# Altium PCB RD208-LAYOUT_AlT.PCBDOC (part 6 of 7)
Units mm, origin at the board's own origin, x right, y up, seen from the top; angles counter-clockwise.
Board outline 240 x 150 mm, 6 copper layers (TOP, Mid-Layer 1, Mid-Layer 2, Mid-Layer 3, Mid-Layer 4, BOTTOM), stack 1.422 mm thick; 773 components, 409 nets, 3936 pads, 97 vias.
Unrouted connection lines stored in the file: 1.
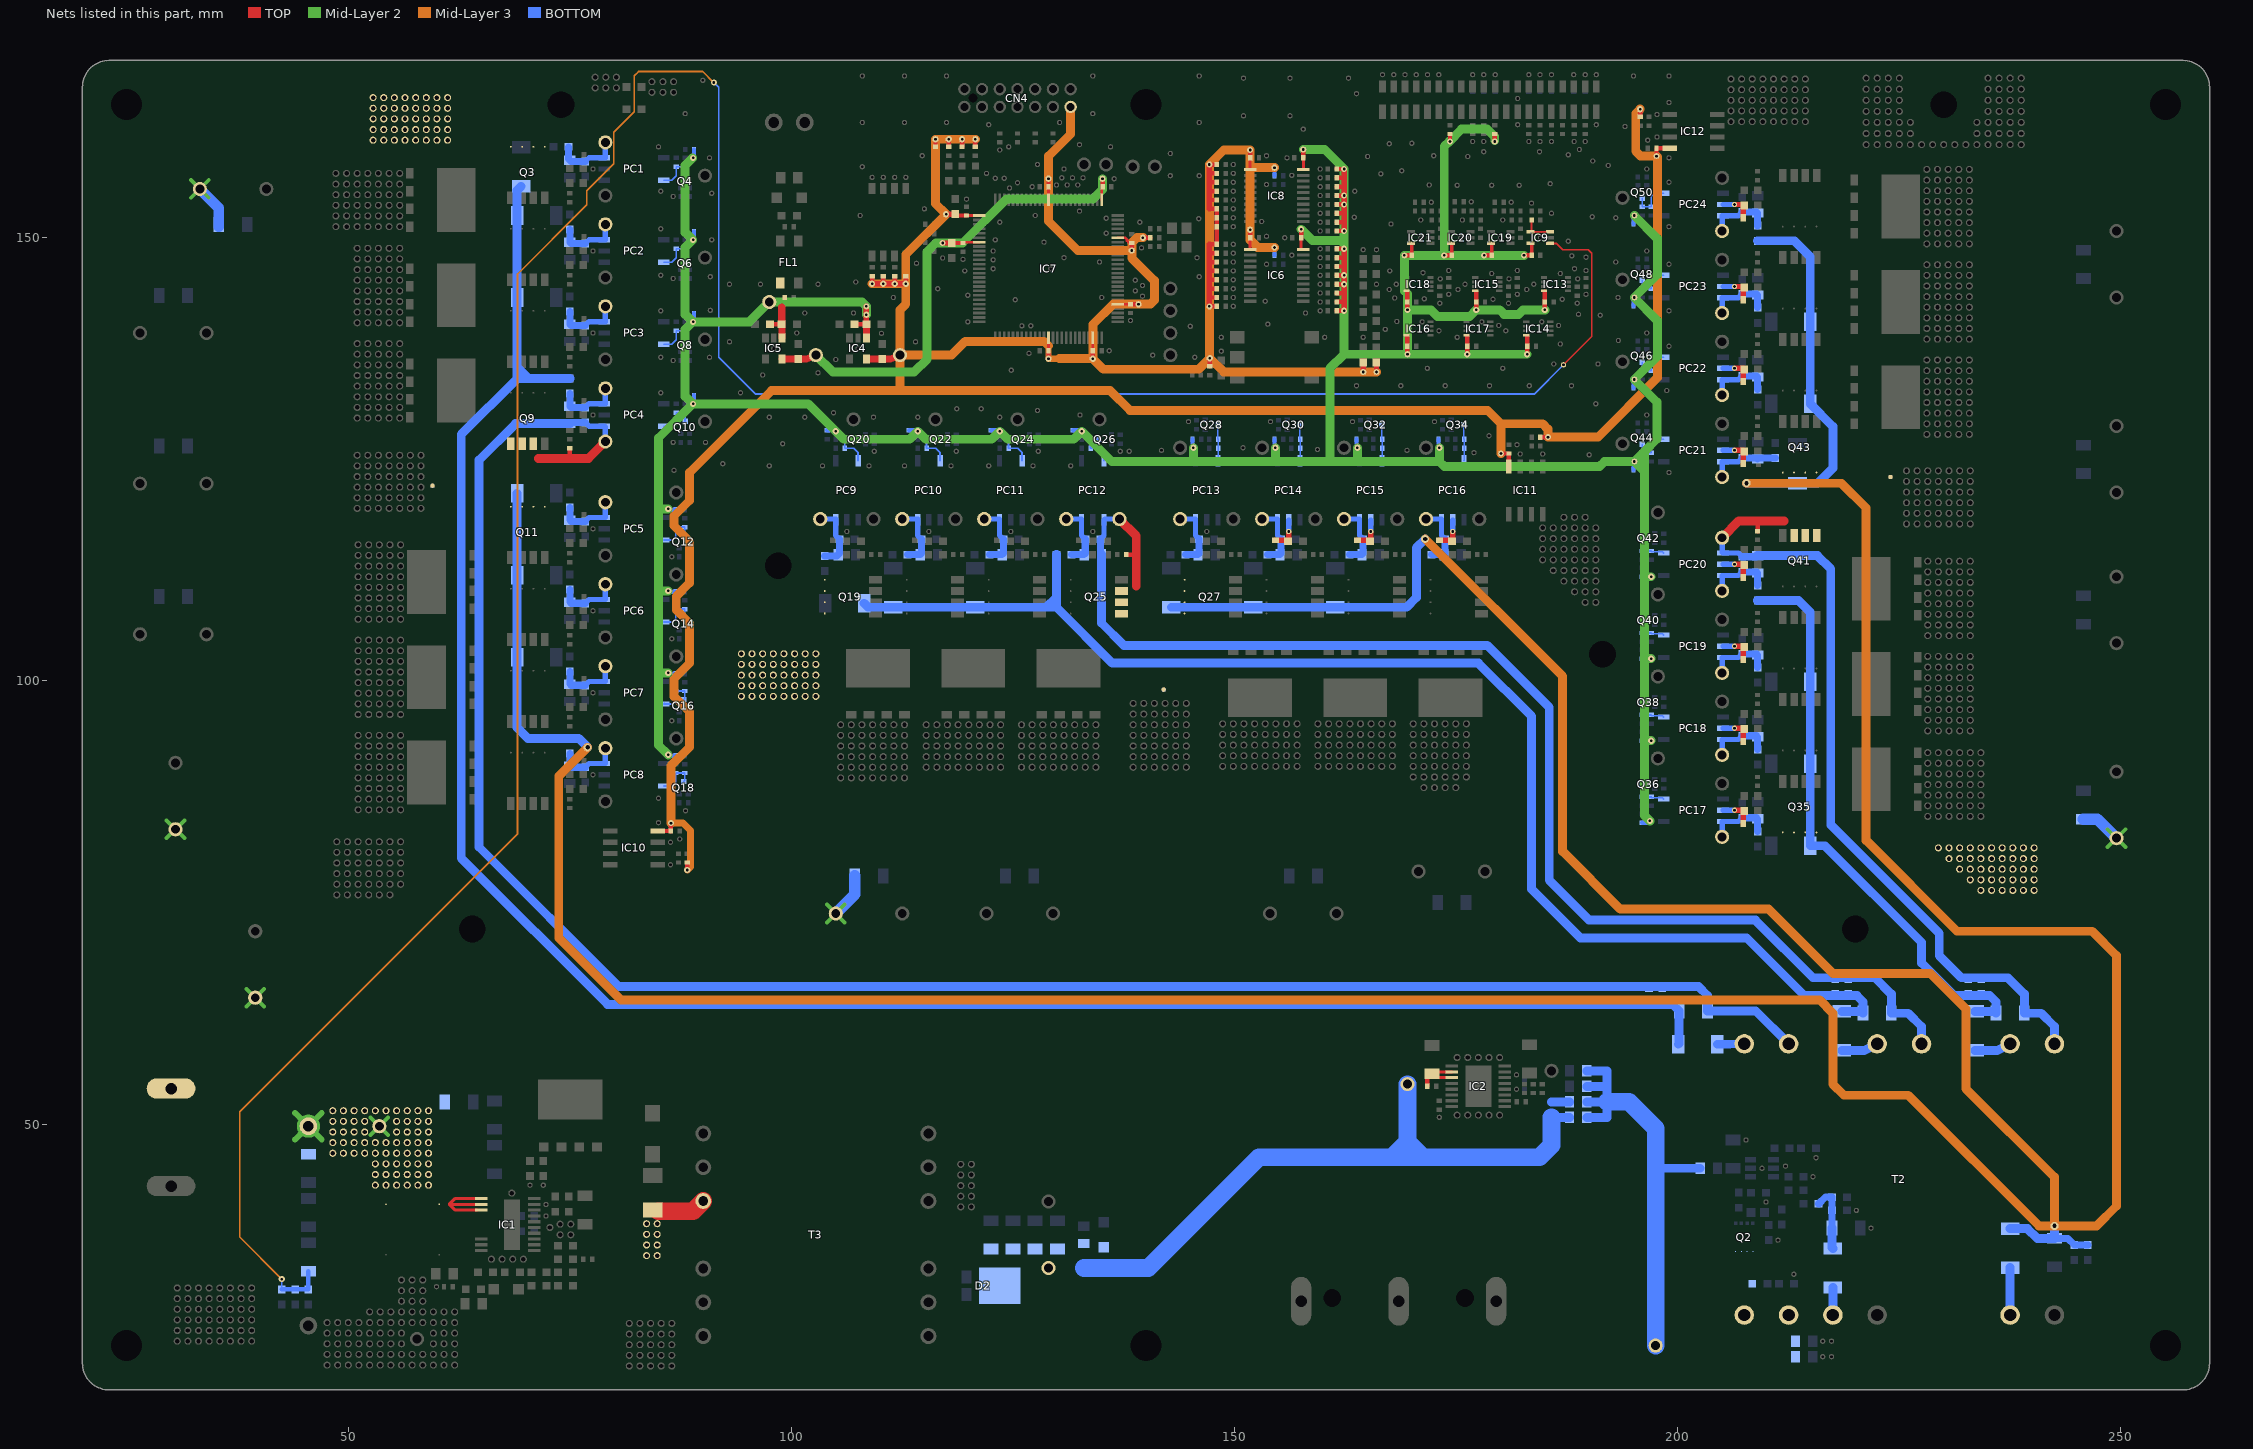
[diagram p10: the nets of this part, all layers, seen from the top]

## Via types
v1: diameter 0.7, hole 0.3, TOP to BOTTOM, 92 vias
v2: diameter 0.9, hole 0.5, TOP to BOTTOM, 4 vias
v3: diameter 1.6, hole 1, TOP to BOTTOM, 1 vias

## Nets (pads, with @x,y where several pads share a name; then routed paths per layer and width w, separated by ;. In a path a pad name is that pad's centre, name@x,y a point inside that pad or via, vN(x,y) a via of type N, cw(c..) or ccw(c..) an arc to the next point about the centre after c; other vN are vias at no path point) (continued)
PC_GD_V6: D63.K pad.@156.1,116.85 PC14.5 R173.1 | length 3.9
  TOP w0.6: D63.K@154.6,115.85 155.9,115.85 R173.1@156,115.75 156.1,115.85 pad.@156.1,116.85
  BOTTOM w0.6: pad.@156.1,116.85 PC14.5@156.1,118.15
PC_GD_V7: D64.K pad.@165.35,116.85 PC15.5 R174.1 | length 3.9
  TOP w0.6: D64.K@163.85,115.85 165.15,115.85 R174.1@165.25,115.75 165.35,115.85 pad.@165.35,116.85
  BOTTOM w0.6: pad.@165.35,116.85 PC15.5@165.35,118.15
PC_GD_V8: D65.K pad.@174.6,116.85 PC16.5 R175.1 | length 3.9
  TOP w0.6: D65.K@173.1,115.85 174.4,115.85 R175.1@174.5,115.75 174.6,115.85 pad.@174.6,116.85
  BOTTOM w0.6: pad.@174.6,116.85 PC16.5@174.6,118.15
PC_GD_W1: D66.K pad.@206.4,85.4 PC17.5 R184.1 | length 3.9
  TOP w0.6: pad.@206.4,85.4 207.4,85.4 R184.1@207.5,85.3 207.4,85.2 D66.K@207.4,83.9
  BOTTOM w0.6: PC17.5@205.1,85.4 pad.@206.4,85.4
PC_GD_W2: D67.K pad.@206.4,94.65 PC18.5 R185.1 | length 3.9
  TOP w0.6: pad.@206.4,94.65 207.4,94.65 R185.1@207.5,94.55 207.4,94.45 D67.K@207.4,93.15
  BOTTOM w0.6: PC18.5@205.1,94.65 pad.@206.4,94.65
PC_GD_W3: D68.K pad.@206.4,103.9 PC19.5 R186.1 | length 3.9
  TOP w0.6: pad.@206.4,103.9 207.4,103.9 R186.1@207.5,103.8 207.4,103.7 D68.K@207.4,102.4
  BOTTOM w0.6: PC19.5@205.1,103.9 pad.@206.4,103.9
PC_GD_W4: D69.K pad.@206.4,113.15 PC20.5 R187.1 | length 3.9
  TOP w0.6: pad.@206.4,113.15 207.4,113.15 R187.1@207.5,113.05 207.4,112.95 D69.K@207.4,111.65
  BOTTOM w0.6: PC20.5@205.1,113.15 pad.@206.4,113.15
PC_GD_W5: D70.K pad.@206.4,126 PC21.5 R188.1 | length 3.9
  TOP w0.6: pad.@206.4,126 207.4,126 R188.1@207.5,125.9 207.4,125.8 D70.K@207.4,124.5
  BOTTOM w0.6: PC21.5@205.1,126 pad.@206.4,126
PC_GD_W6: D71.K pad.@206.4,135.25 PC22.5 R189.1 | length 3.9
  TOP w0.6: pad.@206.4,135.25 207.4,135.25 R189.1@207.5,135.15 207.4,135.05 D71.K@207.4,133.75
  BOTTOM w0.6: PC22.5@205.1,135.25 pad.@206.4,135.25
PC_GD_W7: D72.K pad.@206.4,144.5 PC23.5 R190.1 | length 3.9
  TOP w0.6: pad.@206.4,144.5 207.4,144.5 R190.1@207.5,144.4 207.4,144.3 D72.K@207.4,143
  BOTTOM w0.6: PC23.5@205.1,144.5 pad.@206.4,144.5
PC_GD_W8: D73.K pad.@206.4,153.75 PC24.5 R191.1 | length 3.9
  TOP w0.6: pad.@206.4,153.75 207.4,153.75 R191.1@207.5,153.65 207.4,153.55 D73.K@207.4,152.25
  BOTTOM w0.6: PC24.5@205.1,153.75 pad.@206.4,153.75
PC_V_U1: C47.1 C112.1 PC1.6 R80.1 TP25.1 | length 7.5
  BOTTOM w0.6: C112.1@76.75,158.6 77.17,159.02 PC1.6@78.9,159.02 79,159.02 TP25.1@79,160.75
  BOTTOM w0.8: R80.1@74.85,160.25 74.85,158.875 C47.1@75,158.725 75.125,158.6 C112.1@76.75,158.6
PC_V_U2: C50.1 C113.1 PC2.6 R82.1 TP26.1 | length 7.4
  BOTTOM w0.6: C113.1@76.75,149.35 77.17,149.77 PC2.6@78.9,149.77 79,149.77 TP26.1@79,151.5
  BOTTOM w0.8: R82.1@75,150.9 C50.1@75,149.475 75.125,149.35 C113.1@76.75,149.35
PC_V_U3: C53.1 C114.1 PC3.6 R84.1 TP27.1 | length 7.4
  BOTTOM w0.6: C114.1@76.75,140.1 77.17,140.52 PC3.6@78.9,140.52 79,140.52 TP27.1@79,142.25
  BOTTOM w0.8: R84.1@75,141.65 C53.1@75,140.225 75.125,140.1 C114.1@76.75,140.1
PC_V_U4: C55.1 C115.1 PC4.6 R86.1 TP28.1 | length 7.4
  BOTTOM w0.6: C115.1@76.75,130.85 77.17,131.27 PC4.6@78.9,131.27 79,131.27 TP28.1@79,133
  BOTTOM w0.8: R86.1@75,132.4 C55.1@75,130.975 75.125,130.85 C115.1@76.75,130.85
PC_V_U5: C57.1 C116.1 PC5.6 R88.1 TP29.1 | length 7.4
  BOTTOM w0.6: C116.1@76.75,118 77.17,118.42 PC5.6@78.9,118.42 79,118.42 TP29.1@79,120.15
  BOTTOM w0.8: R88.1@75,119.55 C57.1@75,118.125 75.125,118 C116.1@76.75,118
PC_V_U6: C58.1 C117.1 PC6.6 R90.1 TP30.1 | length 7.4
  BOTTOM w0.6: C117.1@76.75,108.75 77.17,109.17 PC6.6@78.9,109.17 79,109.17 TP30.1@79,110.9
  BOTTOM w0.8: R90.1@75,110.3 C58.1@75,108.875 75.125,108.75 C117.1@76.75,108.75
PC_V_U7: C59.1 C118.1 PC7.6 R92.1 TP31.1 | length 7.4
  BOTTOM w0.6: C118.1@76.75,99.5 77.17,99.92 PC7.6@78.9,99.92 79,99.92 TP31.1@79,101.65
  BOTTOM w0.8: R92.1@75,101.05 C59.1@75,99.625 75.125,99.5 C118.1@76.75,99.5
PC_V_U8: C60.1 C119.1 PC8.6 R94.1 TP32.1 | length 7.4
  BOTTOM w0.6: C119.1@76.75,90.25 77.17,90.67 PC8.6@78.9,90.67 79,90.67 TP32.1@79,92.4
  BOTTOM w0.8: R94.1@75,91.8 C60.1@75,90.375 75.125,90.25 C119.1@76.75,90.25
PC_V_V1: C62.1 C104.1 PC9.6 R96.1 TP41.1 | length 7.5
  BOTTOM w0.6: TP41.1@103.25,118.25 104.98,118.25 PC9.6@104.98,118.15 104.98,116.42 C104.1@105.4,116
  BOTTOM w0.8: R96.1@103.75,114.1 105.125,114.1 C62.1@105.275,114.25 105.4,114.375 C104.1@105.4,116
PC_V_V2: C64.1 C105.1 PC10.6 R98.1 TP42.1 | length 7.4
  BOTTOM w0.6: TP42.1@112.5,118.25 114.23,118.25 PC10.6@114.23,118.15 114.23,116.42 C105.1@114.65,116
  BOTTOM w0.8: R98.1@113.1,114.25 C64.1@114.525,114.25 114.65,114.375 C105.1@114.65,116
PC_V_V3: C68.1 C106.1 PC11.6 R101.1 TP43.1 | length 7.4
  BOTTOM w0.6: TP43.1@121.75,118.25 123.48,118.25 PC11.6@123.48,118.15 123.48,116.42 C106.1@123.9,116
  BOTTOM w0.8: R101.1@122.35,114.25 C68.1@123.775,114.25 123.9,114.375 C106.1@123.9,116
PC_V_V4: C70.1 C107.1 PC12.6 R103.1 TP44.1 | length 7.4
  BOTTOM w0.6: TP44.1@131,118.25 132.73,118.25 PC12.6@132.73,118.15 132.73,116.42 C107.1@133.15,116
  BOTTOM w0.8: R103.1@131.6,114.25 C70.1@133.025,114.25 133.15,114.375 C107.1@133.15,116
PC_V_V5: C72.1 C108.1 PC13.6 R104.1 TP45.1 | length 7.4
  BOTTOM w0.6: TP45.1@143.85,118.25 145.58,118.25 PC13.6@145.58,118.15 145.58,116.42 C108.1@146,116
  BOTTOM w0.8: R104.1@144.45,114.25 C72.1@145.875,114.25 146,114.375 C108.1@146,116
PC_V_V6: C73.1 C109.1 PC14.6 R106.1 TP46.1 | length 7.4
  BOTTOM w0.6: TP46.1@153.1,118.25 154.83,118.25 PC14.6@154.83,118.15 154.83,116.42 C109.1@155.25,116
  BOTTOM w0.8: R106.1@153.7,114.25 C73.1@155.125,114.25 155.25,114.375 C109.1@155.25,116
PC_V_V7: C74.1 C110.1 PC15.6 R108.1 TP47.1 | length 7.4
  BOTTOM w0.6: TP47.1@162.35,118.25 164.08,118.25 PC15.6@164.08,118.15 164.08,116.42 C110.1@164.5,116
  BOTTOM w0.8: R108.1@162.95,114.25 C74.1@164.375,114.25 164.5,114.375 C110.1@164.5,116
PC_V_V8: C76.1 C111.1 PC16.6 R110.1 TP48.1 | length 7.4
  BOTTOM w0.6: TP48.1@171.6,118.25 173.33,118.25 PC16.6@173.33,118.15 173.33,116.42 C111.1@173.75,116
  BOTTOM w0.8: R110.1@172.2,114.25 C76.1@173.625,114.25 173.75,114.375 C111.1@173.75,116
PC_V_W1: C77.1 C120.1 PC17.6 R112.1 TP57.1 | length 7.4
  BOTTOM w0.6: TP57.1@205,82.4 205,84.13 PC17.6@205.1,84.13 206.83,84.13 C120.1@207.25,84.55
  BOTTOM w0.8: C120.1@207.25,84.55 208.875,84.55 C77.1@209,84.425 R112.1@209,83
PC_V_W2: C79.1 C121.1 PC18.6 R114.1 TP58.1 | length 7.4
  BOTTOM w0.6: TP58.1@205,91.65 205,93.38 PC18.6@205.1,93.38 206.83,93.38 C121.1@207.25,93.8
  BOTTOM w0.8: C121.1@207.25,93.8 208.875,93.8 C79.1@209,93.675 R114.1@209,92.25
PC_V_W3: C81.1 C122.1 PC19.6 R116.1 TP59.1 | length 7.4
  BOTTOM w0.6: TP59.1@205,100.9 205,102.63 PC19.6@205.1,102.63 206.83,102.63 C122.1@207.25,103.05
  BOTTOM w0.8: C122.1@207.25,103.05 208.875,103.05 C81.1@209,102.925 R116.1@209,101.5
PC_V_W4: C83.1 C123.1 PC20.6 R118.1 TP60.1 | length 7.4
  BOTTOM w0.6: TP60.1@205,110.15 205,111.88 PC20.6@205.1,111.88 206.83,111.88 C123.1@207.25,112.3
  BOTTOM w0.8: C123.1@207.25,112.3 208.875,112.3 C83.1@209,112.175 R118.1@209,110.75
PC_V_W5: C85.1 C124.1 PC21.6 R120.1 TP61.1 | length 8
  BOTTOM w0.6: TP61.1@205,123 205,124.73 PC21.6@205.1,124.73 206.83,124.73 C124.1@207.25,125.15
  BOTTOM w0.8: C124.1@207.25,125.15 208.875,125.15 C85.1@209,125.025 209.125,125.15 R120.1@211,125.15
PC_V_W6: C86.1 C125.1 PC22.6 R122.1 TP62.1 | length 7.4
  BOTTOM w0.6: TP62.1@205,132.25 205,133.98 PC22.6@205.1,133.98 206.83,133.98 C125.1@207.25,134.4
  BOTTOM w0.8: C125.1@207.25,134.4 208.875,134.4 C86.1@209,134.275 R122.1@209,132.85
PC_V_W7: C87.1 C126.1 PC23.6 R124.1 TP63.1 | length 7.4
  BOTTOM w0.6: TP63.1@205,141.5 205,143.23 PC23.6@205.1,143.23 206.83,143.23 C126.1@207.25,143.65
  BOTTOM w0.8: C126.1@207.25,143.65 208.875,143.65 C87.1@209,143.525 R124.1@209,142.1
PC_V_W8: C88.1 C127.1 PC24.6 R126.1 TP64.1 | length 7.4
  BOTTOM w0.6: TP64.1@205,150.75 205,152.48 PC24.6@205.1,152.48 206.83,152.48 C127.1@207.25,152.9
  BOTTOM w0.8: C127.1@207.25,152.9 208.875,152.9 C88.1@209,152.775 R126.1@209,151.35
PC_VGS_U1: C142.2 PC1.3 Q4.3 R337.2 | length 4.6
  BOTTOM w0.2: PC1.3@85.6,156.48 86.5,156.48 87,156.98 R337.2@87,158 C142.2@88,158 Q4.3@88,157.05
PC_VGS_U2: C143.2 PC2.3 Q6.3 R338.2 | length 4.6
  BOTTOM w0.2: PC2.3@85.6,147.23 86.5,147.23 87,147.73 R338.2@87,148.75 C143.2@88,148.75 Q6.3@88,147.8
PC_VGS_U3: C144.2 PC3.3 Q8.3 R339.2 | length 4.6
  BOTTOM w0.2: PC3.3@85.6,137.98 86.5,137.98 87,138.48 R339.2@87,139.5 C144.2@88,139.5 Q8.3@88,138.55
PC_VGS_U4: C145.2 PC4.3 Q10.3 R340.2 | length 4.6
  BOTTOM w0.2: PC4.3@85.6,128.73 86.5,128.73 87,129.23 R340.2@87,130.25 C145.2@88,130.25 Q10.3@88,129.3
PC_VGS_U5: C146.2 PC5.3 Q12.3 R341.2 | length 4.6
  BOTTOM w0.2: PC5.3@85.6,115.88 86.55,115.88 86.95,116.28 R341.2@86.95,117.35 C146.2@87.95,117.35 87.95,116.5 Q12.3@87.85,116.4
PC_VGS_U6: C147.2 PC6.3 Q14.3 R342.2 | length 4.6
  BOTTOM w0.2: PC6.3@85.6,106.63 86.55,106.63 86.95,107.03 R342.2@86.95,108.1 C147.2@87.95,108.1 87.95,107.25 Q14.3@87.85,107.15
PC_VGS_U7: C148.2 PC7.3 Q16.3 R343.2 | length 4.7
  BOTTOM w0.2: PC7.3@85.67,97.45 PC7.3@85.6,97.38 86.55,97.38 86.95,97.78 R343.2@86.95,98.85 C148.2@87.95,98.85 87.95,98 Q16.3@87.85,97.9
PC_VGS_U8: C149.2 PC8.3 Q18.3 R344.2 | length 4.6
  BOTTOM w0.2: PC8.3@85.6,88.13 86.55,88.13 86.95,88.53 R344.2@86.95,89.6 C149.2@87.95,89.6 87.95,88.75 Q18.3@87.85,88.65
PC_VGS_V1: C150.2 PC9.3 Q20.3 R345.2 | length 4.6
  BOTTOM w0.2: Q20.3@106.95,127.25 C150.2@106,127.25 R345.2@106,126.25 107.02,126.25 107.52,125.75 PC9.3@107.52,124.85
PC_VGS_V2: C151.2 PC10.3 Q22.3 R346.2 | length 4.6
  BOTTOM w0.2: Q22.3@116.2,127.25 C151.2@115.25,127.25 R346.2@115.25,126.25 116.27,126.25 116.77,125.75 PC10.3@116.77,124.85
PC_VGS_V3: C152.2 PC11.3 Q24.3 R347.2 | length 4.6
  BOTTOM w0.2: Q24.3@125.45,127.25 C152.2@124.5,127.25 R347.2@124.5,126.25 125.52,126.25 126.02,125.75 PC11.3@126.02,124.85
PC_VGS_V4: C153.2 PC12.3 Q26.3 R348.2 | length 4.6
  BOTTOM w0.2: Q26.3@134.7,127.25 C153.2@133.75,127.25 R348.2@133.75,126.25 134.77,126.25 135.27,125.75 PC12.3@135.27,124.85
PC_VGS_V5: C154.2 PC13.3 Q28.3 R349.2 | length 4.1
  BOTTOM w0.2: Q28.3@148.1,128.9 148.1,127.3 C154.2@148.15,127.25 R349.2@148.15,126.25 148.15,124.88 PC13.3@148.12,124.85
PC_VGS_V6: C155.2 PC14.3 Q30.3 R350.2 | length 4.1
  BOTTOM w0.2: Q30.3@157.35,128.9 157.35,127.3 C155.2@157.4,127.25 R350.2@157.4,126.25 157.4,124.88 PC14.3@157.37,124.85
PC_VGS_V7: C156.2 PC15.3 Q32.3 R351.2 | length 4.1
  BOTTOM w0.2: Q32.3@166.6,128.9 166.6,127.3 C156.2@166.65,127.25 R351.2@166.65,126.25 166.65,124.88 PC15.3@166.62,124.85
PC_VGS_V8: C157.2 PC16.3 Q34.3 R352.2 | length 4.1
  BOTTOM w0.2: Q34.3@175.85,128.9 175.85,127.3 C157.2@175.9,127.25 R352.2@175.9,126.25 175.9,124.88 PC16.3@175.87,124.85
PC_VGS_W1: C158.2 PC17.3 Q36.3 R353.2 | length 3.9
  BOTTOM w0.2: Q36.3@196,88.35 C158.2@196,86.9 R353.2@197,86.9 197.08,86.82 198.25,86.82 PC17.3@198.4,86.67
PC_VGS_W2: C159.2 PC18.3 Q38.3 R354.2 | length 3.9
  BOTTOM w0.2: Q38.3@196,97.6 C159.2@196,96.15 R354.2@197,96.15 197.08,96.07 198.25,96.07 PC18.3@198.4,95.92
PC_VGS_W3: C160.2 PC19.3 Q40.3 R355.2 | length 3.9
  BOTTOM w0.2: Q40.3@196,106.85 C160.2@196,105.4 R355.2@197,105.4 197.08,105.32 198.25,105.32 PC19.3@198.4,105.17
PC_VGS_W4: C161.2 PC20.3 Q42.3 R356.2 | length 3.9
  BOTTOM w0.2: Q42.3@196,116.1 C161.2@196,114.65 R356.2@197,114.65 197.08,114.57 198.25,114.57 PC20.3@198.4,114.42
PC_VGS_W5: C162.2 PC21.3 Q44.3 R357.2 | length 4.7
  BOTTOM w0.2: Q44.3@196,126.7 C162.2@196,125.75 R357.2@197,125.75 197,126.9 197.37,127.27 PC21.3@198.4,127.27
PC_VGS_W6: C163.2 PC22.3 Q46.3 R358.2 | length 4.7
  BOTTOM w0.2: Q46.3@196,135.95 C163.2@196,135 R358.2@197,135 197,136.15 197.37,136.52 PC22.3@198.4,136.52
PC_VGS_W7: C164.2 PC23.3 Q48.3 R359.2 | length 4.7
  BOTTOM w0.2: Q48.3@196,145.2 C164.2@196,144.25 R359.2@197,144.25 197,145.4 197.37,145.77 PC23.3@198.4,145.77
PC_VGS_W8: C165.2 PC24.3 Q50.3 R360.2 | length 4.7
  BOTTOM w0.2: Q50.3@196,154.45 C165.2@196,153.5 R360.2@197,153.5 197,154.65 197.37,155.02 PC24.3@198.4,155.02
TRANS2_AUX: D10.A T2.3 | length 3.1
  BOTTOM w1: T2.3@217.5,28.45 D10.A@217.5,31.55
TRANS2_AUX_B: C21.1 D10.K R28.1 R31.1 R300.1 | length 7.7
  BOTTOM w0.8: R28.1@215.9,41 216.65,41.75 R300.1@217.4,41.75 R31.1@217.4,40.25 C21.1@217.4,38.25
  BOTTOM w1: C21.1@217.4,38.25 217.4,36.05 D10.K@217.5,35.95
TRANS2_PRI: C128.1 Q2.5 Q2.6 Q2.7 Q2.8 T2.1
TRANS2_SEC1: D7.A T2.16 | length 3.1
  BOTTOM w1: D7.A@204.45,59 205.851,59 T2.16@207.5,59.05
TRANS2_SEC2: D8.A T2.13 | length 4.2
  BOTTOM w1: D8.A@218.5,58.3 221.03,58.3 T2.13@222.5,59.05
TRANS2_SEC3: D9.A T2.10 | length 4.2
  BOTTOM w1: D9.A@233.5,58.3 236.03,58.3 T2.10@237.5,59.05
TRANS2_SEC4: D11.A T2.7 | length 5.4
  BOTTOM w1: T2.7@237.5,28.45 D11.A@237.5,33.8
V_LH: C20.1 D11.K D20.A D22.A D24.A D32.A D34.A D36.A D44.A D46.A D48.A R94.2 R110.2 R126.2 R307.1 R308.1 | length 578.3
  Mid-Layer 3 w1: v2(77,92.5) 73.75,89.25 73.75,71 80.75,64 216,64 217.5,62.5 217.5,54.5 218.75,53.25 226,53.25 240.75,38.5 v2(242.5,38.5) ; v2(171.5,116) 187,100.5 187,80.75 193.5,74.25 210.25,74.25 217.5,67 228.5,67 232.5,63 232.5,54 242.5,44 v2(242.5,38.5) ; v2(207.75,122.3) 218.45,122.3 221.25,119.5 221.25,82 231.5,71.75 246.75,71.75 249.5,69 249.5,40.75 247.25,38.5 v2(242.5,38.5)
  BOTTOM w0.8: C20.1@242.5,37.1 244,37.1 R307.1@244.75,36.35 R308.1@246.25,36.35
  BOTTOM w1: D20.A@69.05,121.15 D22.A@69.05,111.9 D24.A@69.05,102.65 69.05,94.7 70.25,93.5 R94.2@75,93.5 76,93.5 v2(77,92.5) ; D32.A@142.85,108.3 D34.A@152.1,108.3 D36.A@161.35,108.3 169.4,108.3 170.5,109.4 R110.2@170.5,114.25 170.5,115 v2(171.5,116) ; v2(207.75,122.3) D44.A@213.5,122.3 215.8,122.3 217.5,124 217.5,128.7 D46.A@214.95,131.25 D48.A@214.95,140.5 214.95,147.85 213.15,149.65 R126.2@209,149.65 ; D11.K@237.5,38.2 239.45,38.2 240.55,37.1 C20.1@242.5,37.1 v2(242.5,38.5)
V_UH: C17.1 D7.K D14.A D16.A D18.A R86.2 R301.1 R302.1 | length 234.7
  BOTTOM w1: D14.A@69.5,155.8 69.05,155.35 D16.A@69.05,152.5 D18.A@69.05,143.25 69.05,135.4 ; R86.2@75,134.1 70.35,134.1 ; D7.K@200.05,59 200.15,59.1 C17.1@200.15,62.75 199.4,63.5 198.25,63.5 79.25,63.5 62.75,80 62.75,127.8 69.05,134.1 ; 69.05,134.1 69.05,135.4 ; 69.05,134.1 70.35,134.1 ; 69.05,135.4 70.35,134.1
V_UL: C17.2 C55.2 C115.2 DR1.2 PC4.4 Q9.1 Q9.2 Q9.3 Q11.5 Q11.6 Q11.7 Q11.8 R217.2 R301.2 R302.2 T2.15 TP68.1 | length 229
  TOP w0.5: 75,125.1 R217.2@75,126.25
  TOP w1: 71.45,125.1 75,125.1 77.1,125.1 TP68.1@79,127
  BOTTOM w0.6: C115.2@76.75,129.15 77.17,128.73 PC4.4@78.9,128.73 79,128.63 TP68.1@79,127
  BOTTOM w0.8: C55.2@75,129.025 75.125,129.15 C115.2@76.75,129.15
  BOTTOM w1: C55.2@75,129.025 68.875,129.025 64.75,124.9 64.75,81.25 80.5,65.5 202.35,65.5 203.35,64.5 C17.2@203.35,62.75 208.8,62.75 T2.15@212.5,59.05
V_VH: C18.1 D8.K D26.A D28.A D30.A R103.2 R303.1 R304.1 | length 154.1
  BOTTOM w1: D26.A@108.2,108.75 108.65,108.3 D28.A@111.5,108.3 D30.A@120.75,108.3 128.75,108.3 ; R103.2@129.9,114.25 129.9,109.45 ; D8.K@218.5,62.7 220.7,62.7 C18.1@220.9,62.5 220.9,63.8 220.2,64.5 214.25,64.5 207.75,71 189,71 183.5,76.5 183.5,96 177.5,102 136.2,102 129.9,108.3 ; 128.75,108.3 129.9,108.3 ; 128.75,108.3 129.9,109.45 ; 129.9,108.3 129.9,109.45
V_VL: C18.2 C70.2 C107.2 DR2.2 PC12.4 Q25.1 Q25.2 Q25.3 Q27.5 Q27.6 Q27.7 Q27.8 R225.2 R303.2 R304.2 T2.12 TP76.1 | length 149.1
  TOP w0.5: R225.2@137.75,114.25 138.9,114.25
  TOP w1: TP76.1@137,118.25 138.9,116.35 138.9,114.25 138.9,110.7
  BOTTOM w0.6: C107.2@134.85,116 135.27,116.42 PC12.4@135.27,118.15 135.37,118.25 TP76.1@137,118.25
  BOTTOM w0.8: C107.2@134.85,116 134.85,114.375 C70.2@134.975,114.25
  BOTTOM w1: C70.2@134.975,114.25 134.975,106.525 137.5,104 178.5,104 185.5,97 185.5,77.5 190,73 208.75,73 215.25,66.5 222.25,66.5 224.1,64.65 C18.2@224.1,62.5 226,62.5 227.5,61 T2.12@227.5,59.05
V_WH: C19.1 D9.K D38.A D40.A D42.A R118.2 R305.1 R306.1 | length 66.2
  BOTTOM w1: R118.2@209,109.05 213.65,109.05 214.95,107.75 D42.A@214.95,99.9 D40.A@214.95,90.65 D38.A@214.95,81.4 216.6,81.4 227.5,70.5 227.5,68.172 231.172,64.5 235.2,64.5 235.9,63.8 C19.1@235.9,62.5 235.7,62.7 D9.K@233.5,62.7
V_WL: C19.2 C83.2 C123.2 DR3.2 PC20.4 Q41.1 Q41.2 Q41.3 Q43.5 Q43.6 Q43.7 Q43.8 R233.2 R305.2 R306.2 T2.9 TP84.1 | length 91.9
  TOP w0.5: R233.2@209,116.9 209,118.05
  TOP w1: TP84.1@205,116.15 206.9,118.05 209,118.05 212,118.05
  BOTTOM w0.6: TP84.1@205,116.15 205,114.52 PC20.4@205.1,114.42 206.83,114.42 C123.2@207.25,114
  BOTTOM w0.8: C123.2@207.25,114 208.875,114 C83.2@209,114.125
  BOTTOM w1: C83.2@209,114.125 215.75,114.125 217.25,112.625 217.25,83.75 229.5,71.5 229.5,69 232,66.5 237.25,66.5 239.1,64.65 C19.2@239.1,62.5 241,62.5 242.5,61 T2.9@242.5,59.05
VDC: C11.1 C130.1 IC9.1 pad.@187.1,135.65 R10.2 R15.1 | length 320.8
  TOP w0.2: IC9.1@185.6,149.35 186.3,149.35 187,148.65 189.9,148.65 190.3,148.25 190.3,138.85 pad.@187.1,135.65
  Mid-Layer 3 w0.2: v1(42.5,32.5) 37.75,37.25 37.75,51.4 69.1,82.75 69.1,145.9 76.9,153.7 76.9,155.3 79.95,158.35 79.95,161.9 82.25,164.2 82.25,168.25 82.75,168.75 90,168.75 v1(91.25,167.5)
  BOTTOM w0.2: C130.1@42.5,31.35 v1(42.5,32.5) ; v1(91.25,167.5) 91.8,166.95 91.8,136.5 95.95,132.35 183.8,132.35 pad.@187.1,135.65
  BOTTOM w0.5: C130.1@42.5,31.35 C11.1@44,31.35 R15.1@45.5,31.35 R10.2@45.5,33.4
VDC_VF_OUT: IC9.3 IC9.4 R192.1 | length 3.6
  TOP w0.2: R192.1@183.5,152 183.5,150.75 IC9.4@183.4,150.65 IC9.3@185.6,150.65
VP_1R8_CPLD_D: C30.1 C40.1 C41.1 C42.1 IC5.5 IC7.26 IC7.57 TP8.1 | length 60.4
  TOP w0.3: C41.1@119.35,149.4 119.45,149.5 IC7.57@121.2,149.5 ; IC7.26@135,154.3 135,155.65 C42.1@135.1,155.75
  TOP w0.5: C40.1@118.1,149.4 C41.1@119.35,149.4 ; C42.1@135.1,155.75 v1(135.1,156.65)
  TOP w0.6: v1(117.05,149.4) C40.1@118.1,149.4
  TOP w0.8: IC5.5@98.95,136.3 C30.1@100.75,136.3 101.638,136.3 TP8.1@102.75,136.75
  Mid-Layer 2 w1: TP8.1@102.75,136.75 104.65,134.85 113.85,134.85 115.3,136.3 115.3,148.4 116.3,149.4 v1(117.05,149.4) 119.3,149.4 124.25,154.35 134,154.35 135.1,155.45 v1(135.1,156.65)
VP_3R3_PRH_D: C25.1 C31.1 C32.1 C33.1 C34.1 C35.1 C36.1 C37.1 C39.1 C44.1 C61.1 C75.1 C89.1 CN4.2 IC4.5 IC6.1 IC7.5 IC7.20 IC7.38 IC7.51 IC7.88 IC7.98 IC8.1 IC10.8 IC11.8 IC12.8 R48.1 R49.1 R50.1 R51.1 R52.1 R53.1 R54.1 R55.1 R66.1 R67.1 R68.1 R69.1 R70.1 R71.1 R72.1 R73.1 R74.1 R128.1 R129.1 R145.1 R146.1 R147.1 R148.1 R149.1 R150.1 R151.1 R152.1 R153.1 R241.1 R243.1 R289.2 R291.2 R293.2 TP7.1 | length 472.6
  TOP w0.3: C35.1@119.75,152.5 IC7.51@121.2,152.5 ; C36.1@129,137.25 IC7.88@129,138.7 ; IC7.38@129,154.3 C34.1@129,155.75 ; C37.1@134,137.25 IC7.98@134,138.7 ; IC7.5@136.8,142.5 C32.1@138.25,142.5 ; IC7.20@136.8,150 137.65,150 137.85,149.8 137.85,149.65 138,149.5 138.3,149.5 C33.1@138.4,149.4
  TOP w0.35: IC6.1@151.75,148.675 C39.1@151.75,150 ; IC8.1@151.75,157.675 C44.1@151.75,159
  TOP w0.5: IC10.8@84.932,83.055 C61.1@86.395,83.055 ; C61.1@86.4,83.05 v1(86.4,83.95) ; v1(88.25,78.65) R289.2@88.25,79.5 ; v1(109.1,144.8) R149.1@109.1,145.65 ; v1(110.35,144.8) R150.1@110.35,145.65 ; v1(111.65,144.8) R151.1@111.65,145.65 ; v1(112.9,144.8) R152.1@112.9,145.65 ; R148.1@116.25,160.25 v1(116.25,161.1) ; R147.1@117.75,160.25 v1(117.75,161.1) ; C31.1@118.5,152.65 118.65,152.5 C35.1@119.75,152.5 ; R146.1@119.25,160.25 v1(119.25,161.1) ; R145.1@120.75,160.25 v1(120.75,161.1) ; v1(129,136.35) C36.1@129,137.25 ; C34.1@129,155.75 v1(129,156.65) ; v1(134,136.35) C37.1@134,137.25 ; C32.1@138.25,142.5 v1(139.15,142.5) ; v1(138.4,148.55) C33.1@138.4,149.4 ; v1(139.65,150) R74.1@140.5,150 ; v1(147.15,142.25) R55.1@148,142.25 ; 147.15,143.25 R54.1@148,143.25 ; 147.15,144.25 R53.1@148,144.25 ; 147.15,145.25 R52.1@148,145.25 ; 147.15,146.25 R51.1@148,146.25 ; 147.15,147.25 R50.1@148,147.25 ; 147.15,148.25 R49.1@148,148.25 ; 147.15,149.25 R48.1@148,149.25 R73.1@148,151.25 R72.1@148,152.25 R71.1@148,153.25 147.15,153.25 ; 147.15,154.25 R70.1@148,154.25 ; 147.15,155.25 R69.1@148,155.25 ; 147.15,156.25 R68.1@148,156.25 ; 147.15,157.25 R67.1@148,157.25 ; v1(147.15,158.25) R66.1@148,158.25 ; R153.1@147.2,135.5 v1(147.2,136.4) ; C39.1@151.75,150 v1(151.75,150.9) ; C44.1@151.75,159 v1(151.75,159.9) ; v1(180.05,125.65) C75.1@180.95,125.65 ; IC11.8@180.945,124.182 C75.1@180.945,125.645 ; R291.2@184.5,127.5 v1(185.35,127.5) ; R293.2@195.75,163.65 v1(195.75,164.5) ; v1(197.6,159.2) C89.1@197.6,160.1 ; C89.1@197.605,160.095 IC12.8@199.067,160.095
  TOP w0.6: v1(109.1,144.8) v1(110.35,144.8) v1(111.65,144.8) v1(112.9,144.8) ; v1(117.45,152.65) C31.1@118.5,152.65 ; v1(147.15,142.25) 147.15,143.25 147.15,144.25 147.15,145.25 147.15,146.25 147.15,147.25 147.15,148.25 147.15,149.25 ; 147.15,153.25 147.15,154.25 147.15,155.25 147.15,156.25 147.15,157.25 v1(147.15,158.25) ; v1(164.5,134.85) R129.1@164.5,135.9 ; v1(166,134.85) R128.1@166,135.9
  TOP w0.8: IC4.5@108.45,136.3 C25.1@110.25,136.3 111.138,136.3 TP7.1@112.25,136.75
  Mid-Layer 3 w0.7: 129,137.8 v1(129,136.35) 130.25,136.35
  Mid-Layer 3 w0.8: v1(86.4,83.95) 87.75,83.95 88.6,83.1 88.6,79 v1(88.25,78.65)
  Mid-Layer 3 w1: v1(86.4,83.95) 86.4,90.4 88.5,92.5 88.5,96.5 86.75,98.25 86.75,100.25 88.5,102 88.5,106.5 87,108 87,109.55 88.5,111.05 88.5,115.75 86.75,117.5 86.75,118.6 88.5,120.35 88.5,123.5 97.75,132.75 112.25,132.75 ; v1(109.1,144.8) v1(110.35,144.8) v1(111.65,144.8) v1(112.9,144.8) ; v1(120.75,161.1) v1(119.25,161.1) v1(117.75,161.1) v1(116.25,161.1) 116.25,153.85 v1(117.45,152.65) 112.9,148.1 v1(112.9,144.8) ; 129,137.8 128.5,138.3 119.6,138.3 118.05,136.75 TP7.1@112.25,136.75 ; 130.25,136.35 v1(134,136.35) ; CN4.2@131.5,164.75 131.5,161.7 129,159.2 v1(129,156.65) 129,151.85 132.3,148.55 v1(138.4,148.55) ; v1(139.65,150) 138.95,150 138.4,149.45 v1(138.4,148.55) ; v1(154.5,148.9) 152.6,148.9 151.75,149.75 v1(151.75,150.9) 151.75,157.9 ; v1(154.5,157.9) 151.75,157.9 ; v1(166,134.85) v1(164.5,134.85) 148.75,134.85 v1(147.2,136.4) ; v1(180.05,125.65) 180.05,129 ; v1(195.75,164.5) 195.25,164 195.25,159.75 195.8,159.2 v1(197.6,159.2) 197.7,159.1 197.7,134.2 191,127.5 v1(185.35,127.5) 185.35,128.4 184.75,129 180.05,129 ; 112.25,132.75 TP7.1@112.25,136.75 ; 112.25,132.75 135.95,132.75 138.2,130.5 178.55,130.5 180.05,129 ; TP7.1@112.25,136.75 112.25,141.85 112.9,142.5 v1(112.9,144.8) ; v1(134,136.35) 134,140.2 136.3,142.5 v1(139.15,142.5) 140.5,142.5 140.95,142.95 140.95,145.15 138.4,147.7 v1(138.4,148.55) ; v1(134,136.35) 135.2,135.15 145.95,135.15 v1(147.2,136.4) ; v1(147.2,136.4) 147.15,136.45 v1(147.15,142.25) v1(147.15,158.25) 148.8,159.9 v1(151.75,159.9) 151.75,157.9
  BOTTOM w0.5: R241.1@154.5,148 v1(154.5,148.9) ; R243.1@154.5,157 v1(154.5,157.9)
  BOTTOM w0.6: v1(109.1,144.8) v1(110.35,144.8) ; v1(111.65,144.8) v1(112.9,144.8)
VP_5R0_PRH_D: C27.1 C28.1 C29.1 C38.1 C43.1 C45.1 C90.1 C91.1 C92.1 C93.1 C94.1 C95.1 C97.1 C99.1 C101.1 FL1.3 IC4.1 IC5.1 IC6.20 IC8.20 IC9.5 IC13.8 IC14.8 IC15.8 IC16.8 IC17.8 IC18.8 IC19.5 IC20.5 IC21.5 R36.1 R39.1 R40.1 R41.1 R42.1 R43.1 R44.1 R45.1 R46.1 R47.1 R56.2 R57.2 R58.1 R59.1 R60.1 R61.1 R62.1 R63.1 R64.1 R65.1 R81.1 R83.1 R85.1 R87.1 R89.1 R91.1 R93.1 R95.1 R97.1 R99.1 R100.1 R102.1 R105.1 R107.1 R109.1 R111.1 R113.1 R115.1 R117.1 R119.1 R121.1 R123.1 R125.1 R127.1 TP6.1 | length 509.4
  TOP w0.35: IC6.20@157.5,148.675 C38.1@157.5,150 ; IC8.20@157.75,157.675 C43.1@157.75,159
  TOP w0.4: C101.1@170,148 IC21.5@170,149.35 ; C99.1@174.5,148 IC20.5@174.5,149.35 ; C97.1@179,148 IC19.5@179,149.35 ; C45.1@183.5,148 IC9.5@183.5,149.35
  TOP w0.5: R39.1@97.6,140.25 C29.1@98.9,140.25 ; R36.1@107.1,140.25 C28.1@108.4,140.25 ; C38.1@157.5,150 v1(157.5,150.95) ; C43.1@157.75,159 v1(157.75,159.95) ; R47.1@161.5,141.75 v1(162.35,141.75) ; R46.1@161.5,142.75 162.35,142.75 ; R45.1@161.5,143.75 162.35,143.75 ; R44.1@161.5,144.75 v1(162.35,144.75) ; R43.1@161.5,145.75 v1(162.35,145.75) ; R42.1@161.5,146.75 162.35,146.75 ; R41.1@161.5,147.75 162.35,147.75 ; R40.1@161.5,148.75 v1(162.35,148.75) ; R65.1@161.5,150.75 v1(162.35,150.75) ; R64.1@161.5,151.75 162.35,151.75 ; R63.1@161.5,152.75 162.35,152.75 ; R62.1@161.5,153.75 v1(162.35,153.75) ; R61.1@161.5,154.75 v1(162.35,154.75) ; R60.1@161.5,155.75 162.35,155.75 ; R59.1@161.5,156.75 162.35,156.75 ; R58.1@161.5,157.75 v1(162.35,157.75) ; v1(169.15,148) C101.1@170,148 ; v1(169.5,136.85) C94.1@169.5,137.75 IC16.8@169.5,138.9 ; v1(169.5,141.85) C95.1@169.5,142.75 IC18.8@169.5,143.9 ; v1(173.65,148) C99.1@174.5,148 ; v1(174.3,160.85) R57.2@174.3,161.7 ; v1(176.25,136.85) C93.1@176.25,137.75 IC17.8@176.25,138.9 ; v1(177.25,141.85) C92.1@177.25,142.75 IC15.8@177.25,143.9 ; v1(178.15,148) C97.1@179,148 ; v1(179.35,160.85) R56.2@179.35,161.7 ; v1(182.65,148) C45.1@183.5,148 ; v1(183,136.85) C91.1@183,137.75 IC14.8@183,138.9 ; v1(185,141.85) C90.1@185,142.75 IC13.8@185,143.9
  TOP w0.6: C28.1@108.45,140.25 v1(108.45,141.3) v1(108.45,142.25) ; v1(162.35,141.75) 162.35,142.75 162.35,143.75 v1(162.35,144.75) v1(162.35,145.75) 162.35,146.75 162.35,147.75 v1(162.35,148.75) ; v1(162.35,150.75) 162.35,151.75 162.35,152.75 v1(162.35,153.75) v1(162.35,154.75) 162.35,155.75 162.35,156.75 v1(162.35,157.75)
  TOP w0.8: 98.9,142.2 C29.1@98.9,140.25 98.95,140.2 IC5.1@98.95,138.7 ; C28.1@108.4,140.25 108.45,140.2 IC4.1@108.45,138.7
  Mid-Layer 2 w1: v1(86.1,91.65) 85,92.75 85,100.9 ; v1(86.1,100.9) 85,100.9 ; v1(86.1,110.15) 85,110.15 ; v1(86.1,119.4) 85,119.4 ; v1@88.85,159 88,158.15 88,150.6 88.85,149.75 88,148.9 88,141.35 v1@88.85,140.5 ; v1(108.45,141.3) v1(108.45,142.25) 107.95,142.75 TP6.1@97.5,142.75 95.25,140.5 v1(88.9,140.5) v1@88.85,140.5 ; v1(145.35,126.3) 145.35,124.75 ; v1(154.6,126.3) 154.6,124.75 ; v1(157.5,150.95) 158.75,149.7 162.3,149.7 162.35,149.65 ; v1(157.75,159.95) 160.15,159.95 v1(162.35,157.75) v1(162.35,154.75) v1(162.35,153.75) v1(162.35,150.75) 162.35,149.65 ; v1(163.85,126.3) 163.85,124.75 ; v1(173.1,126.3) 173.1,124.75 ; v1@179.35,160.95 179.35,161.4 178.5,162.25 175.6,162.25 174.25,160.9 173.65,160.3 v1(173.65,148) ; v1(182.65,148) v1(178.15,148) v1(173.65,148) ; v1(183,136.85) v1(176.25,136.85) v1(169.5,136.85) ; v1(185,141.85) 182.55,141.85 182.05,141.35 180.4,141.35 179.9,141.85 v1(177.25,141.85) 176.5,141.1 172.9,141.1 172.15,141.85 v1(169.5,141.85) ; v1(195.1,152.5) 197.7,149.9 197.7,145.85 v1(195.1,143.25) 197.7,140.65 197.7,136.6 v1(195.1,134) 197.65,131.45 197.65,127.3 196.25,125.9 ; v1(196.85,84.2) 196.25,84.8 196.25,93.25 ; v1(197,93.25) 196.25,93.25 ; v1(197,102.5) 196.25,102.5 ; v1(197,111.75) 196.25,111.75 ; 85,100.9 85,110.15 ; 85,110.15 85,119.4 ; 85,119.4 85,127.4 v1@88.85,131.25 ; v1@88.85,131.25 88,132.1 88,139.65 v1@88.85,140.5 ; v1@88.85,131.25 v1(88.9,131.25) 101.9,131.25 v1(105,128.15) 105.9,127.25 113.35,127.25 v1(114.25,128.15) 115.15,127.25 122.6,127.25 v1(123.5,128.15) 124.4,127.25 131.85,127.25 v1(132.75,128.15) 136.15,124.75 145.35,124.75 ; 145.35,124.75 154.6,124.75 ; 154.6,124.75 160.75,124.75 ; 160.75,124.75 163.85,124.75 ; 160.75,124.75 160.75,135.25 162.35,136.85 ; 162.35,136.85 v1(169.5,136.85) ; 162.35,136.85 v1(162.35,141.75) v1(162.35,144.75) v1(162.35,145.75) v1(162.35,148.75) 162.35,149.65 ; 163.85,124.75 173.1,124.75 ; v1(169.5,136.85) v1(169.5,141.85) ; v1(169.5,141.85) 169.5,143.65 169.15,144 v1(169.15,148) v1(173.65,148) ; 173.1,124.75 173.65,124.2 191.2,124.2 191.75,124.75 v1(195.1,124.75) ; v1(195.1,124.75) 196.25,123.6 ; v1(195.1,124.75) 196.25,125.9 ; 196.25,93.25 196.25,102.5 ; 196.25,102.5 196.25,111.75 ; 196.25,111.75 196.25,123.6 ; 196.25,123.6 196.25,125.9
  BOTTOM w0.5: v1(86.1,91.65) 86.2,91.55 R95.1@86.95,91.55 ; v1(86.1,100.9) 86.2,100.8 R93.1@86.95,100.8 ; v1(86.1,110.15) 86.2,110.05 R91.1@86.95,110.05 ; v1(86.1,119.4) 86.2,119.3 R89.1@86.95,119.3 ; v1(88.9,131.25) 89,131.35 R87.1@89,132.2 ; v1(88.9,140.5) 89,140.6 R85.1@89,141.45 ; v1(88.9,149.75) 89,149.85 R83.1@89,150.7 ; v1(88.9,159) 89,159.1 R81.1@89,159.95 ; R97.1@104.05,128.25 104.9,128.25 v1(105,128.15) ; R99.1@113.3,128.25 114.15,128.25 v1(114.25,128.15) ; R100.1@122.55,128.25 123.4,128.25 v1(123.5,128.15) ; R102.1@131.8,128.25 132.65,128.25 v1(132.75,128.15) ; R105.1@145.25,127.25 145.25,126.4 v1(145.35,126.3) ; R107.1@154.5,127.25 154.5,126.4 v1(154.6,126.3) ; R109.1@163.75,127.25 163.75,126.4 v1(163.85,126.3) ; R111.1@173,127.25 173,126.4 v1(173.1,126.3) ; R121.1@195,123.8 195,124.65 v1(195.1,124.75) ; R123.1@195,133.05 195,133.9 v1(195.1,134) ; R125.1@195,142.3 195,143.15 v1(195.1,143.25) ; R127.1@195,151.55 195,152.4 v1(195.1,152.5) ; R113.1@196,84 196.65,84 v1(196.85,84.2) ; R115.1@196,93.25 v1(197,93.25) ; R117.1@196,102.5 v1(197,102.5) ; R119.1@196,111.75 v1(197,111.75)
  BOTTOM w0.6: v1(108.45,141.3) v1(108.45,142.25)
VP_15R0_INV_ISO: C137.1 C138.1 R20.2 R21.2 R23.2 R25.2 R155.1 T2.2 TP5.1 | length 50.6
  BOTTOM w1: R20.2@189.725,50.75 192,50.75 192,52.5 ; R23.2@189.725,52.5 192,52.5 ; R25.2@189.725,54.25 192,54.25 ; R21.2@189.725,56 192,56 192,54.25 ; 197.5,45 R155.1@202.525,45 ; 192,52.5 192,54.25
  BOTTOM w2: 192,52.5 194.5,52.5 197.5,49.5 197.5,45 TP5.1@197.5,25
VP_15R0_INV_LDO: C6.1 C7.1 C9.1 C15.1 C131.1 C132.1 D2.3 D3.K IC2.10 IC2.11 R8.2 R20.1 R22.1 R23.1 TP3.1 | length 85.3
  TOP w0.35: IC2.11@174.513,55.225 172.675,55.225 C15.1@172.25,55.65 172.475,55.875 IC2.10@174.513,55.875
  TOP w0.5: R22.1@171.75,54.25 171.75,55.15 C15.1@172.25,55.65
  BOTTOM w1: 185.75,50.75 R20.1@187.775,50.75 ; 185.75,52.5 R23.1@187.775,52.5
  BOTTOM w2: 133,33.75 140.25,33.75 152.75,46.25 167.75,46.25 ; TP3.1@169.5,54.5 169.5,48 ; 185.75,50.75 185.75,47.6 184.4,46.25 171.25,46.25 ; 167.75,46.25 169.5,46.25 ; 167.75,46.25 169.5,48 ; 169.5,46.25 169.5,48 ; 169.5,46.25 171.25,46.25 ; 169.5,48 171.25,46.25
VP_380R0_INV: C1.1 C2.1 C3.1 C48.1 C63.1 C66.1 C67.1 C78.1 CN1.1 D4.A IC1.1 IC1.2 IC1.3 pad.@48.25,46.7 pad.@48.25,47.9 pad.@48.25,49.1 pad.@48.25,50.3 pad.@48.25,51.5 pad.@49.45,46.7 pad.@49.45,47.9 pad.@49.45,49.1 pad.@49.45,50.3 pad.@49.45,51.5 pad.@50.65,46.7 pad.@50.65,47.9 pad.@50.65,49.1 pad.@50.65,50.3 pad.@50.65,51.5 pad.@51.85,46.7 pad.@51.85,47.9 pad.@51.85,49.1 pad.@51.85,50.3 pad.@51.85,51.5 pad.@52.8,161 pad.@52.8,162.2 pad.@52.8,163.4 pad.@52.8,164.6 pad.@52.8,165.8 pad.@53.05,43.1 pad.@53.05,44.3 pad.@53.05,45.5 pad.@53.05,46.7 pad.@53.05,47.9 pad.@53.05,51.5 pad.@54,161 pad.@54,162.2 pad.@54,163.4 pad.@54,164.6 pad.@54,165.8 pad.@54.25,43.1 pad.@54.25,44.3 pad.@54.25,45.5 pad.@54.25,46.7 pad.@54.25,47.9 pad.@54.25,51.5 pad.@55.2,161 pad.@55.2,162.2 pad.@55.2,163.4 pad.@55.2,164.6 pad.@55.2,165.8 pad.@55.45,43.1 pad.@55.45,44.3 pad.@55.45,45.5 pad.@55.45,46.7 pad.@55.45,47.9 pad.@55.45,49.1 pad.@55.45,50.3 pad.@55.45,51.5 pad.@56.4,161 pad.@56.4,162.2 pad.@56.4,163.4 pad.@56.4,164.6 pad.@56.4,165.8 pad.@56.65,43.1 pad.@56.65,44.3 pad.@56.65,45.5 pad.@56.65,46.7 pad.@56.65,47.9 pad.@56.65,49.1 pad.@56.65,50.3 pad.@56.65,51.5 pad.@57.6,161 pad.@57.6,162.2 pad.@57.6,163.4 pad.@57.6,164.6 pad.@57.6,165.8 pad.@57.85,43.1 pad.@57.85,44.3 pad.@57.85,45.5 pad.@57.85,46.7 pad.@57.85,47.9 pad.@57.85,49.1 pad.@57.85,50.3 pad.@57.85,51.5 pad.@58.8,161 pad.@58.8,162.2 pad.@58.8,163.4 pad.@58.8,164.6 pad.@58.8,165.8 pad.@59.05,43.1 pad.@59.05,44.3 pad.@59.05,45.5 pad.@59.05,46.7 pad.@59.05,47.9 pad.@59.05,49.1 pad.@59.05,50.3 pad.@59.05,51.5 pad.@60,161 pad.@60,162.2 pad.@60,163.4 pad.@60,164.6 pad.@60,165.8 pad.@61.2,161 pad.@61.2,162.2 pad.@61.2,163.4 pad.@61.2,164.6 pad.@61.2,165.8 pad.@83.65,35.15 pad.@83.65,36.35 pad.@83.65,37.55 pad.@83.65,38.75 pad.@84.85,35.15 pad.@84.85,36.35 pad.@84.85,37.55 pad.@84.85,38.75 pad.@94.35,98.25 pad.@94.35,99.45 pad.@94.35,100.65 pad.@94.35,101.85 pad.@94.35,103.05 pad.@95.55,98.25 pad.@95.55,99.45 pad.@95.55,100.65 pad.@95.55,101.85 pad.@95.55,103.05 pad.@96.75,98.25 pad.@96.75,99.45 pad.@96.75,100.65 pad.@96.75,101.85 pad.@96.75,103.05 pad.@97.95,98.25 pad.@97.95,99.45 pad.@97.95,100.65 pad.@97.95,101.85 pad.@97.95,103.05 pad.@99.15,98.25 pad.@99.15,99.45 pad.@99.15,100.65 pad.@99.15,101.85 pad.@99.15,103.05 pad.@100.35,98.25 pad.@100.35,99.45 pad.@100.35,100.65 pad.@100.35,101.85 pad.@100.35,103.05 pad.@101.55,98.25 pad.@101.55,99.45 pad.@101.55,100.65 pad.@101.55,101.85 pad.@101.55,103.05 pad.@102.75,98.25 pad.@102.75,99.45 pad.@102.75,100.65 pad.@102.75,101.85 pad.@102.75,103.05 pad.@229.4,81.15 pad.@230.6,79.95 pad.@230.6,81.15 pad.@231.8,78.75 pad.@231.8,79.95 pad.@231.8,81.15 pad.@233,77.55 pad.@233,78.75 pad.@233,79.95 pad.@233,81.15 pad.@234.2,76.35 pad.@234.2,77.55 pad.@234.2,78.75 pad.@234.2,79.95 pad.@234.2,81.15 pad.@235.4,76.35 pad.@235.4,77.55 pad.@235.4,78.75 pad.@235.4,79.95 pad.@235.4,81.15 pad.@236.6,76.35 pad.@236.6,77.55 pad.@236.6,78.75 pad.@236.6,79.95 pad.@236.6,81.15 pad.@237.8,76.35 pad.@237.8,77.55 pad.@237.8,78.75 pad.@237.8,79.95 pad.@237.8,81.15 pad.@239,76.35 pad.@239,77.55 pad.@239,78.75 pad.@239,79.95 pad.@239,81.15 pad.@240.2,76.35 pad.@240.2,77.55 pad.@240.2,78.75 pad.@240.2,79.95 pad.@240.2,81.15 Q3.5 Q3.6 Q3.7 Q3.8 Q19.5 Q19.6 Q19.7 Q19.8 Q35.5 Q35.6 Q35.7 Q35.8 R1.1 R5.1 R193.1 R199.1 R203.1 T3.3 TP1.1 | length 76.8
  TOP w0.35: IC1.3@64.512,40.275 62.075,40.275 61.4,40.95 ; IC1.2@64.512,40.925 61.425,40.925 61.4,40.95 ; IC1.1@64.512,41.575 62.025,41.575 61.4,40.95
  TOP w2: D4.A@85,40.15 88.89,40.15 T3.3@90.05,41.31
  Mid-Layer 2 w0.44: 29.5,82.25 C67.1@30.5,83.25 ; 29.5,84.25 C67.1@30.5,83.25 ; 31.5,82.25 C67.1@30.5,83.25 ; 31.5,84.25 C67.1@30.5,83.25 ; 32.25,154.5 C48.1@33.25,155.5 ; 32.25,156.5 C48.1@33.25,155.5 ; 34.25,154.5 C48.1@33.25,155.5 ; 34.25,156.5 C48.1@33.25,155.5 ; 38.5,63.25 C66.1@39.5,64.25 ; 38.5,65.25 C66.1@39.5,64.25 ; 40.5,63.25 C66.1@39.5,64.25 ; 40.5,65.25 C66.1@39.5,64.25 ; 52.5,48.75 TP1.1@53.5,49.75 ; 52.5,50.75 TP1.1@53.5,49.75 ; 54.5,48.75 TP1.1@53.5,49.75 ; 54.5,50.75 TP1.1@53.5,49.75 ; 104,72.75 C63.1@105,73.75 ; 104,74.75 C63.1@105,73.75 ; 106,72.75 C63.1@105,73.75 ; 106,74.75 C63.1@105,73.75 ; 248.5,81.25 C78.1@249.5,82.25 ; 248.5,83.25 C78.1@249.5,82.25 ; 250.5,81.25 C78.1@249.5,82.25 ; 250.5,83.25 C78.1@249.5,82.25
  Mid-Layer 2 w0.66: 44,48.25 45.04,49.29 C1.1@45.5,49.75 ; 44,51.25 45.04,50.21 C1.1@45.5,49.75 ; 47,48.25 45.96,49.29 C1.1@45.5,49.75 ; 47,51.25 45.96,50.21 C1.1@45.5,49.75
  Mid-Layer 2 w1.3: 45.04,49.29 cw(c45.5,49.75) 45.04,50.21 cw(c45.5,49.75) 45.96,50.21 cw(c45.5,49.75) 46.15,49.75 cw(c45.5,49.75) 45.96,49.29 cw(c45.5,49.75) 45.04,49.29
  BOTTOM w1.2: C48.1@33.25,155.5 35.4,153.35 R193.1@35.4,151.5 R193.1@35.4,151.25
  BOTTOM w1.3: C63.1@105,73.75 107.15,75.9 R199.1@107.15,78 ; R203.1@245.75,84.4 247.35,84.4 C78.1@249.5,82.25
pads on no net: CN3.7 CN3.17 CN3.18 CN3.27 CN3.30 CN3.32 CN3.34 CN4. CN4.12 CN4.14 D15.1 D15.2 D17.1 D17.2 D19.1 D19.2 D21.1 D21.2 D23.1 D23.2 D25.1 D25.2 D27.1 D27.2 D29.1 D29.2 D31.1 D31.2 D33.1 D33.2 D35.1 D35.2 D37.1 D37.2 D39.1 D39.2 D41.1 D41.2 D43.1 D43.2 D45.1 D45.2 D47.1 D47.2 D49.1 D49.2 IC2.13 IC2.14 IC4.4 IC5.4 IC7.1 IC7.2 IC7.3 IC7.4 IC7.6 IC7.15 IC7.16 IC7.17 IC7.18 IC7.19 IC7.29 IC7.37 IC7.39 IC7.40 IC7.41 IC7.42 IC7.43 IC7.44 IC7.46 IC7.59 IC7.63 IC7.64 IC7.74 IC7.86 IC7.87 IC7.97 IC16.3 T3.2 T3.4 T3.7 T3.12

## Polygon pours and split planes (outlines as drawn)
no net on Top Overlay "TOPOVERLAY172" (solid, pour order 0): 23 vertices, not listed, extent 135.156,54.49 137.772,57.513
no net on Top Overlay "TOPOVERLAY173" (solid, pour order 0): 18 vertices, not listed, extent 137.882,54.491 140.967,57.509
no net on Top Overlay "TOPOVERLAY174" (solid, pour order 0): 38 vertices, not listed, extent 123.928,54.44 126.792,57.56
V_VL on TOP "TOP56" (solid, pour order 142): 27 vertices, not listed, extent 136.8,98.25 148.65,111.65
V_UL on TOP "TOP61" (solid, pour order 147): 25 vertices, not listed, extent 59.1,115.35 72.4,127.2
HVV_3_4 on TOP "TOP1" (solid, pour order 87): 17 vertices, not listed, extent 148.25,89.95 157.45,100.25
HVV_2_4 on TOP "TOP2" (solid, pour order 88): 17 vertices, not listed, extent 159,89.95 168.2,100.25
HVU_1_4 on TOP "TOP3" (solid, pour order 89): 17 vertices, not listed, extent 50.7,85.05 61,94.25
HVU_2_4 on TOP "TOP4" (solid, pour order 90): 17 vertices, not listed, extent 50.7,95.8 61,105
HVU_3_4 on TOP "TOP5" (solid, pour order 91): 17 vertices, not listed, extent 50.7,106.55 61,115.75
HVV_1_4 on TOP "TOP6" (solid, pour order 92): 21 vertices, not listed, extent 169.75,87.55 178.95,100.25
GND on TOP "TOP7" (solid, pour order 93): 21 vertices, not listed, extent 183.2,108.45 191.3,118.9
GND on TOP "TOP8" (solid, pour order 94): 21 vertices, not listed, extent 65.7,33.925 70.25,37
GND on TOP "TOP9" (solid, pour order 95): 38 vertices, not listed, extent 71.95,31.35 78.65,39.407
VP_380R0_INV on TOP "TOP10" (solid, pour order 96): 22 vertices, not listed, extent 93.45,97.85 108.05,111.7
5V_RTN on TOP "TOP11" (solid, pour order 97): 25 vertices, not listed, extent 100.15,149 102.5,164.05
5V_IN on TOP "TOP12" (solid, pour order 98): 25 vertices, not listed, extent 97,149 99.35,164.05
VP_5R0_PRH_D on TOP "TOP13" (solid, pour order 99): 17 vertices, not listed, extent 97.5,141.95 99.5,145.5
GND_D on TOP "TOP14" (solid, pour order 100): 100.15,141.5 cw(c100.15,141.65) 100,141.65 100,143.596 cw(c100.25,143.596) 100.073,143.773 100.227,143.927 ccw(c100.05,144.103) 100.3,144.104 100.3,145.25 cw(c100.55,145.25) 100.55,145.5 100.95,145.5 cw(c100.95,145.25) 101.2,145.25 101.2,141.65 cw(c101.05,141.65) 101.05,141.5
HVW_1_4 on TOP "TOP15" (solid, pour order 101): 17 vertices, not listed, extent 223,148.9 233.3,158.1
HVW_2_4 on TOP "TOP16" (solid, pour order 102): 17 vertices, not listed, extent 223,138.15 233.3,147.35
HVW_3_4 on TOP "TOP17" (solid, pour order 103): 17 vertices, not listed, extent 223,127.4 233.3,136.6
PC_G_W8 on TOP "TOP18" (solid, pour order 104): 213.15,156.55 cw(c213.15,156.8) 212.9,156.8 212.9,157.8 ccw(c212.65,157.8) 212.65,158.05 204.7,158.05 cw(c204.7,158.3) 204.45,158.3 204.45,161.5 cw(c204.6,161.5) 204.6,161.65 215.65,161.65 cw(c215.65,161.4) 215.9,161.4 215.9,156.8 cw(c215.65,156.8) 215.65,156.55
VP_380R0_INV on TOP "TOP19" (solid, pour order 105): 20 vertices, not listed, extent 52,156 72.5,169
LDO_15VOUT on TOP "TOP20" (solid, pour order 106): 19 vertices, not listed, extent 181.5,55.15 186.75,57
GND on TOP "TOP21" (solid, pour order 107): 21 vertices, not listed, extent 173.8,49.95 183.1,52.8
GND on TOP "TOP22" (solid, pour order 108): 17 vertices, not listed, extent 173.35,55.75 182.15,60.25
LT8316_SENSE_B on TOP "TOP23" (solid, pour order 109): 74.6,41.35 cw(c74.6,41.5) 74.45,41.5 74.45,42.65 73.544,43.556 cw(c73.65,43.662) 73.5,43.662 73.5,47.65 cw(c73.75,47.65) 73.75,47.9 78.35,47.9 cw(c78.35,47.65) 78.6,47.65 78.6,41.912 cw(c78.45,41.912) 78.556,41.806 78.144,41.394 cw(c78.038,41.5) 78.038,41.35
N16129695 on TOP "TOP24" (solid, pour order 110): 83.4,43.35 cw(c83.4,43.45) 83.3,43.45 83.3,45.309 cw(c83.4,45.309) 83.329,45.379 83.45,45.5 83.45,47.4 cw(c83.55,47.4) 83.55,47.5 85.05,47.5 cw(c85.05,47.4) 85.15,47.4 85.15,45.5 85.371,45.279 cw(c85.3,45.209) 85.4,45.209 85.4,43.45 cw(c85.3,43.45) 85.3,43.35
PC_G_U1 on TOP "TOP25" (solid, pour order 111): 23 vertices, not listed, extent 60,146.7 72.4,157.65
PC_G_U2 on TOP "TOP26" (solid, pour order 112): 26 vertices, not listed, extent 60,137.45 72.4,146.9
PC_G_U3 on TOP "TOP27" (solid, pour order 113): 20 vertices, not listed, extent 60,128.2 72.4,136.45
PC_G_U5 on TOP "TOP28" (solid, pour order 114): 21 vertices, not listed, extent 63.65,106.1 72.4,114.75
PC_G_U6 on TOP "TOP29" (solid, pour order 115): 17 vertices, not listed, extent 63.65,96.85 72.4,105.1
PC_G_U7 on TOP "TOP30" (solid, pour order 116): 21 vertices, not listed, extent 63.65,87.6 72.4,95.85
PC_G_U8 on TOP "TOP31" (solid, pour order 117): 68.35,81.5 cw(c68.35,81.75) 68.1,81.75 68.1,86.35 cw(c68.35,86.35) 68.35,86.6 71.05,86.6 cw(c71.05,86.35) 71.3,86.35 71.3,85.35 ccw(c71.55,85.35) 71.55,85.1 79.3,85.1 cw(c79.3,84.85) 79.55,84.85 79.55,81.65 cw(c79.4,81.65) 79.4,81.5
PC_G_V1 on TOP "TOP32" (solid, pour order 118): 23 vertices, not listed, extent 106.35,99.25 117.3,111.65
PC_G_V2 on TOP "TOP33" (solid, pour order 119): 26 vertices, not listed, extent 117.1,99.25 126.55,111.65
PC_G_V3 on TOP "TOP34" (solid, pour order 120): 20 vertices, not listed, extent 127.55,99.25 135.8,111.65
PC_G_V5 on TOP "TOP35" (solid, pour order 121): 21 vertices, not listed, extent 149.25,102.9 157.9,111.65
PC_G_V6 on TOP "TOP36" (solid, pour order 122): 17 vertices, not listed, extent 158.9,102.9 167.15,111.65
PC_G_V7 on TOP "TOP37" (solid, pour order 123): 21 vertices, not listed, extent 168.15,102.9 176.4,111.65
PC_G_V8 on TOP "TOP38" (solid, pour order 124): 177.65,107.35 cw(c177.65,107.6) 177.4,107.6 177.4,110.3 cw(c177.65,110.3) 177.65,110.55 178.65,110.55 ccw(c178.65,110.8) 178.9,110.8 178.9,118.55 cw(c179.15,118.55) 179.15,118.8 182.35,118.8 cw(c182.35,118.65) 182.5,118.65 182.5,107.6 cw(c182.25,107.6) 182.25,107.35
PC_G_W7 on TOP "TOP39" (solid, pour order 125): 21 vertices, not listed, extent 211.6,147.3 220.35,155.55
PC_G_W6 on TOP "TOP40" (solid, pour order 126): 17 vertices, not listed, extent 211.6,138.05 220.35,146.3
PC_G_W5 on TOP "TOP41" (solid, pour order 127): 21 vertices, not listed, extent 211.6,128.4 220.35,137.05
PC_G_W3 on TOP "TOP42" (solid, pour order 128): 20 vertices, not listed, extent 211.6,106.7 224,114.95
PC_G_W2 on TOP "TOP43" (solid, pour order 129): 26 vertices, not listed, extent 211.6,96.25 224,105.7
PC_G_W1 on TOP "TOP44" (solid, pour order 130): 23 vertices, not listed, extent 211.6,85.5 224,96.45
GND on TOP "TOP45" (solid, pour order 131): 19 vertices, not listed, extent 67.95,40.2 70.9,43.45
VP_15R0_INV_LDO on TOP "TOP46" (solid, pour order 132): 21 vertices, not listed, extent 168.5,53.7 173.1,56.25
GND on TOP "TOP47" (solid, pour order 133): 118.95,40.25 cw(c118.95,40.5) 118.7,40.5 118.7,45.6 cw(c118.95,45.6) 118.95,45.85 120.45,45.85 cw(c120.45,45.6) 120.7,45.6 120.7,40.5 cw(c120.45,40.5) 120.45,40.25
GND_D on TOP "TOP48" (solid, pour order 134): 168.557,139.85 cw(c168.557,140) 168.451,139.894 167.194,141.151 cw(c167.3,141.257) 167.15,141.257 167.15,143.45 cw(c167.3,143.45) 167.3,143.6 168.25,143.6 cw(c168.25,143.45) 168.4,143.45 168.4,141.75 ccw(c168.75,141.75) 168.502,141.502 168.756,141.249 cw(c168.65,141.143) 168.8,141.143 168.8,140 cw(c168.65,140) 168.65,139.85
VP_380R0_INV on TOP "TOP49" (solid, pour order 135): 23 vertices, not listed, extent 22,40.1 63.05,57.5
GND on TOP "TOP50" (solid, pour order 136): 22 vertices, not listed, extent 48.3,60.4 78.5,83.5
GND on TOP "TOP51" (solid, pour order 137): 30 vertices, not listed, extent 77.45,162.5 81.85,169
HVV_3_4 on TOP "TOP52" (solid, pour order 138): 105.4,88.65 cw(c105.4,88.9) 105.15,88.9 105.15,95.25 cw(c105.4,95.25) 105.4,95.5 109.9,95.5 ccw(c109.9,95.75) 110.15,95.75 110.15,96.35 cw(c110.4,96.35) 110.4,96.6 113.1,96.6 cw(c113.1,96.35) 113.35,96.35 113.35,88.9 cw(c113.1,88.9) 113.1,88.65
HVV_2_4 on TOP "TOP53" (solid, pour order 139): 115.05,89.85 cw(c115.05,90.1) 114.8,90.1 114.8,95.25 cw(c115.05,95.25) 115.05,95.5 120.65,95.5 ccw(c120.65,95.75) 120.9,95.75 120.9,96.35 cw(c121.15,96.35) 121.15,96.6 123.85,96.6 cw(c123.85,96.35) 124.1,96.35 124.1,90.1 cw(c123.85,90.1) 123.85,89.85
HVV_1_4 on TOP "TOP54" (solid, pour order 140): 125.8,89.85 cw(c125.8,90.1) 125.55,90.1 125.55,95.25 cw(c125.8,95.25) 125.8,95.5 131.4,95.5 ccw(c131.4,95.75) 131.65,95.75 131.65,96.35 cw(c131.9,96.35) 131.9,96.6 134.6,96.6 cw(c134.6,96.35) 134.85,96.35 134.85,90.1 cw(c134.6,90.1) 134.6,89.85
OUT_V on TOP "TOP55" (solid, pour order 141): 138.1,89.75 cw(c138.1,90) 137.85,90 137.85,99.3 cw(c138.1,99.3) 138.1,99.55 145,99.55 cw(c145,99.3) 145.25,99.3 145.25,90 cw(c145,90) 145,89.75
HVU_3_4 on TOP "TOP57" (solid, pour order 143): 48.45,150.65 cw(c48.45,150.9) 48.2,150.9 48.2,157.5 cw(c48.45,157.5) 48.45,157.75 56,157.75 cw(c56,157.5) 56.25,157.5 56.25,154.1 ccw(c56.5,154.1) 56.5,153.85 57.1,153.85 cw(c57.1,153.6) 57.35,153.6 57.35,150.9 cw(c57.1,150.9) 57.1,150.65
HVU_2_4 on TOP "TOP58" (solid, pour order 144): 50.85,139.9 cw(c50.85,140.15) 50.6,140.15 50.6,149 cw(c50.85,149) 50.85,149.25 56,149.25 cw(c56,149) 56.25,149 56.25,143.35 ccw(c56.5,143.35) 56.5,143.1 57.1,143.1 cw(c57.1,142.85) 57.35,142.85 57.35,140.15 cw(c57.1,140.15) 57.1,139.9
HVU_1_4 on TOP "TOP59" (solid, pour order 145): 50.85,129.15 cw(c50.85,129.4) 50.6,129.4 50.6,138.3 cw(c50.85,138.3) 50.85,138.55 56,138.55 cw(c56,138.3) 56.25,138.3 56.25,132.6 ccw(c56.5,132.6) 56.5,132.35 57.1,132.35 cw(c57.1,132.1) 57.35,132.1 57.35,129.4 cw(c57.1,129.4) 57.1,129.15
OUT_U on TOP "TOP60" (solid, pour order 146): 50.85,118.75 cw(c50.85,119) 50.6,119 50.6,125.9 cw(c50.85,125.9) 50.85,126.15 62.55,126.15 cw(c62.55,125.9) 62.8,125.9 62.8,119 cw(c62.55,119) 62.55,118.75
HVW_3_4 on TOP "TOP62" (solid, pour order 148): 228,84.3 cw(c228,84.55) 227.75,84.55 227.75,89.05 ccw(c227.5,89.05) 227.5,89.3 226.9,89.3 cw(c226.9,89.55) 226.65,89.55 226.65,92.25 cw(c226.9,92.25) 226.9,92.5 234.35,92.5 cw(c234.35,92.25) 234.6,92.25 234.6,84.55 cw(c234.35,84.55) 234.35,84.3
HVW_2_4 on TOP "TOP63" (solid, pour order 149): 228,93.9 cw(c228,94.15) 227.75,94.15 227.75,99.8 ccw(c227.5,99.8) 227.5,100.05 226.9,100.05 cw(c226.9,100.3) 226.65,100.3 226.65,103 cw(c226.9,103) 226.9,103.25 233.15,103.25 cw(c233.15,103) 233.4,103 233.4,94.15 cw(c233.15,94.15) 233.15,93.9
HVW_1_4 on TOP "TOP64" (solid, pour order 150): 228,104.65 cw(c228,104.9) 227.75,104.9 227.75,110.55 ccw(c227.5,110.55) 227.5,110.8 226.9,110.8 cw(c226.9,111.05) 226.65,111.05 226.65,113.75 cw(c226.9,113.75) 226.9,114 233.15,114 cw(c233.15,113.75) 233.4,113.75 233.4,104.9 cw(c233.15,104.9) 233.15,104.65
OUT_W on TOP "TOP65" (solid, pour order 151): 223.05,117 cw(c223.05,117.25) 222.8,117.25 222.8,124.15 cw(c223.05,124.15) 223.05,124.4 233.25,124.4 cw(c233.25,124.15) 233.5,124.15 233.5,117.25 cw(c233.25,117.25) 233.25,117
VP_380R0_INV on TOP "TOP67" (solid, pour order 153): 22 vertices, not listed, extent 211,66.25 240.65,87.15
VP_380R0_INV on TOP "TOP69" (solid, pour order 155): 83.5,34.7 cw(c83.5,34.95) 83.25,34.95 83.25,40.9 cw(c83.5,40.9) 83.5,41.15 86.3,41.15 cw(c86.3,40.9) 86.55,40.9 86.55,37.119 ccw(c90.05,33.69) 85.267,34.753 cw(c85.043,35.2) 85.043,34.7
GND_D on TOP "TOP72" (solid, pour order 158): 157 vertices, not listed, extent 82.65,81 95.3,169
GND on TOP "TOP73" (solid, pour order 159): 46 vertices, not listed, extent 21,21 90.95,44.5
GND_D on TOP "TOP74" (solid, pour order 160): 97 vertices, not listed, extent 172.45,141.6 181.284,150.3
GND_D on TOP "TOP76" (solid, pour order 162): 35 vertices, not listed, extent 167.035,151.1 176.25,161.1
GND_D on TOP "TOP77" (solid, pour order 163): 80 vertices, not listed, extent 178.3,141.6 189.173,150.3
GND_D on TOP "TOP78" (solid, pour order 164): 32 vertices, not listed, extent 169.3,151.1 180.75,161.5
GND_D on TOP "TOP79" (solid, pour order 165): 40 vertices, not listed, extent 182.8,146.867 189.95,150.3
GND_D on TOP "TOP80" (solid, pour order 166): 23 vertices, not listed, extent 174.448,153.55 184,160.355
GND on TOP "TOP82" (solid, pour order 168): 19 vertices, not listed, extent 205.5,159.5 239.75,169
GND_D on TOP "TOP68" (solid, pour order 154): 60 vertices, not listed, extent 138.75,146.9 146.75,152.6
GND_D on TOP "TOP70" (solid, pour order 156): 25 vertices, not listed, extent 135.55,133 149.696,137.75
GND_D on TOP "TOP71" (solid, pour order 157): 170 vertices, not listed, extent 91.55,123.7 191.827,135.85
GND_D on TOP "TOP75" (solid, pour order 161): 70 vertices, not listed, extent 166.1,141.6 172.35,157.527
GND_D on TOP "TOP81" (solid, pour order 167): 830 vertices, not listed, extent 92.25,121.823 199.55,169
V_WL on TOP "TOP66" (solid, pour order 152): 29 vertices, not listed, extent 211.6,115.95 224.75,127.8
HVU_2_4 on Mid-Layer 1 "MID184" (solid, pour order 78): 29 vertices, not listed, extent 21,95.75 56.4,149.25
HVW_2_4 on Mid-Layer 1 "MID186" (solid, pour order 80): 25 vertices, not listed, extent 227.6,93.9 252.5,147.4
HVV_2_4 on Mid-Layer 1 "MID187" (solid, pour order 81): 128.75,72.5 128.75,72.85 128.868,72.85 ccw(c129.5,73.75) 130.132,72.85 130.3,72.85 130.3,72.5
GND on Mid-Layer 1 "MID188" (solid, pour order 82): 248.75,149.5 248.75,149.9 248.802,149.9 ccw(c249.5,150.75) 250.198,149.9 250.25,149.9 250.25,149.5
HVV_2_4 on Mid-Layer 1 "MID189" (solid, pour order 83): 153.25,72.5 153.25,72.85 153.368,72.85 ccw(c154,73.75) 154.632,72.85 154.85,72.85 154.85,72.5
HVV_2_4 on Mid-Layer 1 "MID190" (solid, pour order 84): 33 vertices, not listed, extent 114.75,72.5 168.25,95.65
GND_D on Mid-Layer 1 "MID183" (solid, pour order 77): 30 vertices, not listed, extent 134.8,147.25 146.75,152.6
GND_D on Mid-Layer 1 "MID185" (solid, pour order 79): 39 vertices, not listed, extent 83.75,78.2 199.55,169
GND on Mid-Layer 1 "MID191" (solid, pour order 85): 99 vertices, not listed, extent 21,35.5 222.5,147.1
GND on Mid-Layer 1 "MID192" (solid, pour order 86): 37 vertices, not listed, extent 203.95,145.45 259,169
GND_D on Mid-Layer 2 "MID295" (solid, pour order 68): 53 vertices, not listed, extent 84.45,78.2 135.345,130.5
